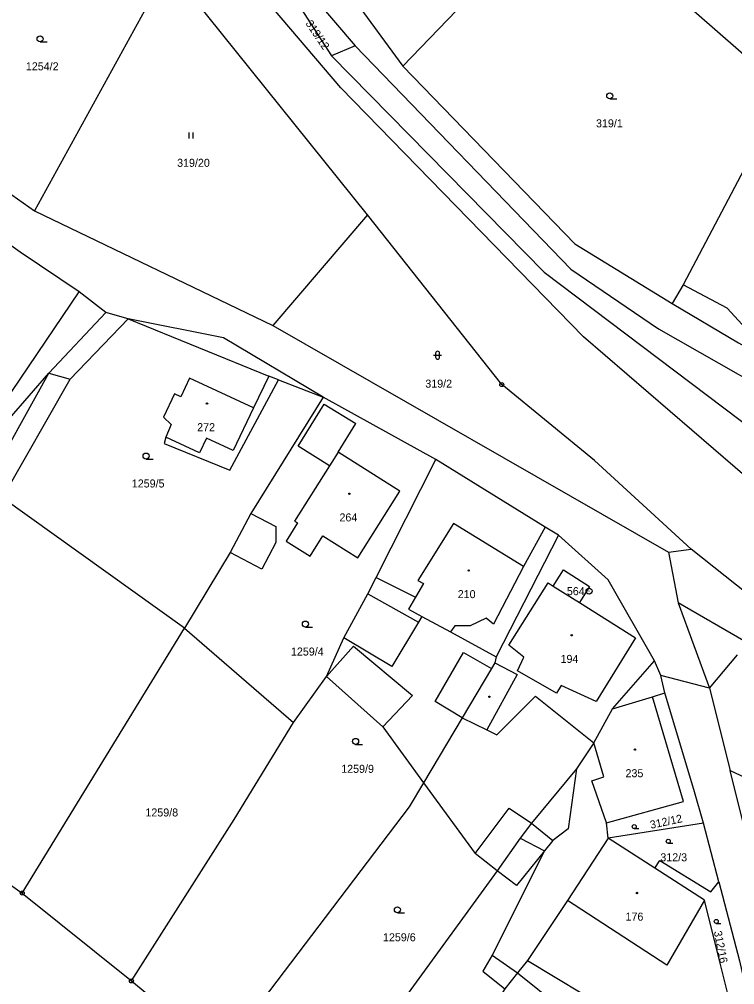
# Model space of a CAD drawing. Extents: x -745926 to -742978, y -968282 to -965689.
# Drawn here: x -745276.5 to -745187.1, y -967037.5 to -966916.9 of the extents above; entities that cross this region are included whole.
import ezdxf

# ---------------------------------------------------------------- set-up
doc = ezdxf.new("R2010")
doc.units = 0
for name, color, linetype in [('Hranice parcel', 7, 'Continuous'), ('Parcelní čísla', 7, 'Continuous'), ('Poz předměty', 7, 'Continuous'), ('Vnitřní kresba', 7, 'Continuous'), ('Značky bodu BP', 7, 'Continuous'), ('Značky budov', 7, 'Continuous'), ('Značky kultur', 7, 'Continuous')]:
    doc.layers.add(name, color=color, linetype=linetype)

msp = doc.modelspace()

# ---------------------------------------------------------------- linework, layer by layer
at = {"layer": 'Hranice parcel'}
for p, q in [((-745180.55, -966926.05), (-745208.11, -966901.93)), ((-745249.76, -966902.34), (-745237.49, -966921.45)), ((-745249.76, -966902.34), (-745234.53, -966920.19)), ((-745239.47, -966907.89), (-745228.55, -966922.71)), ((-745233, -966941.3), (-745257.76, -966910.48)), ((-745259.41, -966913.16), (-745274.6, -966940.8)), ((-745234.53, -966920.19), (-745237.49, -966921.45)), ((-745274.6, -966940.8), (-745244.81, -966955.11)), ((-745233, -966941.3), (-745244.81, -966955.11)), ((-745270.13, -966961.82), (-745262.91, -966954.27)), ((-745244.81, -966955.11), (-745195.35, -966983.42)), ((-745224.43, -966971.87), (-745238.53, -966964.08)), ((-745210.8, -966980.3), (-745224.43, -966971.87)), ((-745209.1, -966981.3), (-745210.8, -966980.3)), ((-745209.1, -966981.3), (-745216.9, -966996.5)), ((-745195.35, -966983.42), (-745192.52, -966983.04)), ((-745195.35, -966983.42), (-745194.15, -966989.75)), ((-745194.15, -966989.75), (-745190.26, -967000.41)), ((-745276.14, -967026.01), (-745255.84, -966992.94)), ((-745255.84, -966992.94), (-745242.24, -967004.7)), ((-745196.33, -966998.82), (-745197.1, -966997)), ((-745190.26, -967000.41), (-745196.33, -966998.82)), ((-745195.83, -967001.01), (-745196.33, -966998.82)), ((-745190.26, -967000.41), (-745187.66, -967010.71)), ((-745187.66, -967010.71), (-745185.09, -967011.89)), ((-745185.48, -967019.4), (-745187.66, -967010.71)), ((-745191.01, -967017.27), (-745202.9, -967019.17)), ((-745189.08, -967024.61), (-745191.01, -967017.27)), ((-745284.25, -967020.3), (-745276.14, -967026.01)), ((-745213.9, -967019.17), (-745210.87, -967020.73)), ((-745197.09, -967022.9), (-745202.9, -967019.17)), ((-745190.87, -967026.9), (-745197.09, -967022.9)), ((-745190.06, -967025.85), (-745189.08, -967024.61)), ((-745276.14, -967026.01), (-745262.49, -967036.98)), ((-745213, -967034.43), (-745214.25, -967035.97)), ((-745214.25, -967035.97), (-745208.81, -967040.3)), ((-745262.49, -967036.98), (-745251.29, -967046.18))]:
    msp.add_line(p, q, dxfattribs=at)
for points in [[(-745228.55, -966922.71), (-745214, -966907.56), (-745210.46, -966904.18)], [(-745296.89, -966915.01), (-745295, -966919.3), (-745292.7, -966924.7), (-745284.5, -966933.2), (-745279.6, -966937.3), (-745274.6, -966940.8)], [(-745234.53, -966920.19), (-745207.57, -966948.09), (-745196.62, -966955.54), (-745176.42, -966967.01), (-745160.97, -966979.85)], [(-745237.49, -966921.45), (-745210.92, -966948.46), (-745176.19, -966974.63), (-745163.93, -966984.87)], [(-745228.55, -966922.71), (-745207.08, -966944.94), (-745194.89, -966952.37)], [(-745180.55, -966926.05), (-745184.33, -966932.61), (-745193.54, -966950.05), (-745194.89, -966952.37)], [(-745269.03, -966950.92), (-745276.41, -966945.96), (-745284.62, -966940.07)], [(-745192.52, -966983.04), (-745204.6, -966972), (-745216.2, -966962.5), (-745233, -966941.3)], [(-745294.07, -966977.76), (-745279.56, -966966.43), (-745269.03, -966950.92)], [(-745262.91, -966954.27), (-745265.7, -966953.5), (-745269.03, -966950.92)], [(-745194.89, -966952.37), (-745186.63, -966957.3), (-745183.99, -966958.75), (-745174.52, -966964.81), (-745165.14, -966972.37), (-745161.18, -966973.19), (-745160.07, -966972.06)], [(-745238.53, -966964.08), (-745250.96, -966956.64), (-745262.91, -966954.27)], [(-745297.5, -967010), (-745294.66, -966999.59), (-745285.71, -966987.42), (-745282.67, -966972.4), (-745272.81, -966961.09), (-745270.13, -966961.82)], [(-745255.84, -966992.94), (-745278.61, -966976.66), (-745270.13, -966961.82)], [(-745255.22, -966961.71), (-745256.32, -966964.02), (-745257.09, -966963.65), (-745258.49, -966966.57), (-745257.5, -966967.5), (-745258.17, -966969.07), (-745258.38, -966969.86), (-745250.17, -966973.19), (-745244.09, -966961.92), (-745245.33, -966961.44), (-745247.23, -966965.42), (-745255.22, -966961.71)], [(-745238.53, -966964.08), (-745247.57, -966978.59), (-745250.16, -966983.48), (-745255.84, -966992.94)], [(-745242.09, -966979.55), (-745241.73, -966979.77), (-745243.16, -966982.04), (-745240.15, -966983.93), (-745238.55, -966981.39), (-745234.19, -966984.14), (-745228.96, -966975.81), (-745236.67, -966970.94), (-745237.73, -966972.63), (-745242.09, -966979.55)], [(-745242.24, -967004.7), (-745238.1, -966998.96), (-745235.95, -966994.13), (-745232.96, -966988.63), (-745231.91, -966986.58), (-745224.43, -966971.87)], [(-745210.8, -966980.3), (-745213.5, -966985.23), (-745222.22, -966979.86), (-745226.68, -966986.95), (-745226, -966987.35), (-745227, -966989.07), (-745227.87, -966990.56), (-745226.19, -966991.46), (-745222.6, -966993.38), (-745216.9, -966996.5)], [(-745197.1, -966997), (-745202.9, -966986.9), (-745209.1, -966981.3)], [(-744949.24, -967094.01), (-745019.94, -967072.91), (-745023.12, -967071.72), (-745025.11, -967070.97), (-745031.23, -967068.81), (-745033.88, -967067.77), (-745037.92, -967066.16), (-745085.77, -967047.22), (-745088.65, -967046.08), (-745106.77, -967038.91), (-745143.53, -967017.02), (-745180, -966993), (-745192.52, -966983.04)], [(-745163.31, -967008.4), (-745185.95, -966994.52), (-745194.15, -966989.75)], [(-745216.9, -966996.5), (-745217.07, -966997.26), (-745217.48, -966997.94), (-745221.16, -967004.14)], [(-745204.72, -967007.26), (-745202.36, -967003), (-745197.1, -966997)], [(-745202.9, -967019.17), (-745203.11, -967017.22), (-745193.48, -967014.55), (-745197.38, -967001.48), (-745195.83, -967001.01)], [(-745191.01, -967017.27), (-745192.12, -967013.35), (-745195.83, -967001.01)], [(-745221.16, -967004.14), (-745218.08, -967005.6), (-745216.84, -967006.24), (-745211.97, -967001.43), (-745204.72, -967007.26)], [(-745221.16, -967004.14), (-745225.97, -967012.23), (-745227.76, -967015.24), (-745251.29, -967046.18)], [(-745262.49, -967036.98), (-745249.66, -967016.81), (-745242.24, -967004.7)], [(-745204.72, -967007.26), (-745206.85, -967010.49), (-745212.49, -967017.26), (-745213.9, -967019.17)], [(-745213.9, -967019.17), (-745216.8, -967023.23), (-745240.35, -967055.61)], [(-745202.9, -967019.17), (-745207.97, -967026.92), (-745211.83, -967032.7), (-745213, -967034.43)], [(-745210.87, -967020.73), (-745217.39, -967033.77), (-745214.25, -967035.97)], [(-745197.09, -967022.9), (-745196.47, -967021.93), (-745190.06, -967025.85)], [(-745189.08, -967024.61), (-745186.49, -967034.46), (-745184.74, -967042.18)], [(-745187.27, -967042.62), (-745187.96, -967038.61), (-745188.97, -967034.61), (-745190.87, -967026.9)], [(-745214.25, -967035.97), (-745215.81, -967037.95), (-745222.69, -967048.89), (-745237.4, -967072.23), (-745240.22, -967071.25)]]:
    msp.add_lwpolyline(points, dxfattribs=at)
at = {"layer": 'Poz předměty'}
for p, q in [((-745236.31, -966925.45), (-745250.92, -966908.25)), ((-745205.98, -966956.55), (-745236.31, -966925.45)), ((-745176.95, -966981.55), (-745205.98, -966956.55))]:
    msp.add_line(p, q, dxfattribs=at)
at = {"layer": 'Vnitřní kresba'}
for p, q in [((-745188.03, -966952.97), (-745193.54, -966950.05)), ((-745272.81, -966961.09), (-745265.7, -966953.5)), ((-745183.84, -966957.56), (-745188.03, -966952.97)), ((-745262.91, -966954.27), (-745245.33, -966961.44)), ((-745280.51, -966974.94), (-745272.81, -966961.09)), ((-745244.09, -966961.92), (-745238.53, -966964.08)), ((-745247.23, -966965.42), (-745249.77, -966970.73)), ((-745241.64, -966970.21), (-745238.38, -966964.94)), ((-745238.38, -966964.94), (-745234.45, -966967.37)), ((-745236.67, -966970.94), (-745234.45, -966967.37)), ((-745253.96, -966971.03), (-745258.17, -966969.07)), ((-745253.1, -966969.2), (-745253.96, -966971.03)), ((-745249.77, -966970.73), (-745253.1, -966969.2)), ((-745237.73, -966972.63), (-745241.64, -966970.21)), ((-745247.57, -966978.59), (-745244.45, -966980.24)), ((-745244.45, -966980.24), (-745244.44, -966982.24)), ((-745244.44, -966982.24), (-745246.2, -966985.57)), ((-745246.2, -966985.57), (-745250.16, -966983.48)), ((-745213.5, -966985.23), (-745217.24, -966992.44)), ((-745231.91, -966986.58), (-745227, -966989.07)), ((-745209.78, -966987.67), (-745208.51, -966985.65)), ((-745208.51, -966985.65), (-745205.23, -966987.71)), ((-745215.33, -966995.05), (-745210.42, -966987.27)), ((-745210.42, -966987.27), (-745209.78, -966987.67)), ((-745209.78, -966987.67), (-745206.49, -966989.73)), ((-745205.23, -966987.71), (-745206.49, -966989.73)), ((-745232.96, -966988.63), (-745226.61, -966992.16)), ((-745206.49, -966989.73), (-745199.48, -966994.14)), ((-745226.61, -966992.16), (-745229.93, -966997.72)), ((-745226.19, -966991.46), (-745226.61, -966992.16)), ((-745222.07, -966992.61), (-745222.6, -966993.38)), ((-745220.15, -966992.65), (-745222.07, -966992.61)), ((-745218.16, -966991.66), (-745220.15, -966992.65)), ((-745217.24, -966992.44), (-745218.16, -966991.66)), ((-745229.93, -966997.72), (-745235.95, -966994.13)), ((-745199.48, -966994.14), (-745204.39, -967002.07)), ((-745238.1, -966998.96), (-745234.73, -966995.17)), ((-745234.73, -966995.17), (-745227.35, -967001.33)), ((-745224.51, -967002.07), (-745221, -966995.97)), ((-745221, -966995.97), (-745217.48, -966997.94)), ((-745213.45, -966996.55), (-745215.33, -966995.05)), ((-745217.07, -966997.26), (-745214.28, -966998.72)), ((-745214.25, -966998.24), (-745213.45, -966996.55)), ((-745190.26, -967000.41), (-745186.74, -966996.27)), ((-745209.37, -967001.03), (-745214.25, -966998.24)), ((-745231.05, -967005.26), (-745238.1, -966998.96)), ((-745214.28, -966998.72), (-745218.08, -967005.6)), ((-745208.8, -967000.1), (-745209.37, -967001.03)), ((-745204.39, -967002.07), (-745208.8, -967000.1)), ((-745227.35, -967001.33), (-745231.05, -967005.26)), ((-745221.16, -967004.14), (-745224.51, -967002.07)), ((-745202.36, -967003), (-745197.38, -967001.48)), ((-745231.05, -967005.26), (-745225.97, -967012.23)), ((-745203.47, -967011.51), (-745204.72, -967007.26)), ((-745206.85, -967010.49), (-745207.9, -967018)), ((-745204.94, -967011.97), (-745203.47, -967011.51)), ((-745225.97, -967012.23), (-745219.55, -967021.05)), ((-745203.11, -967017.22), (-745204.94, -967011.97)), ((-745219.55, -967021.05), (-745215.26, -967015.4)), ((-745215.26, -967015.4), (-745212.49, -967017.26)), ((-745212.49, -967017.26), (-745209.82, -967019.43)), ((-745207.9, -967018), (-745209.82, -967019.43)), ((-745209.82, -967019.43), (-745210.87, -967020.73)), ((-745216.8, -967023.23), (-745219.55, -967021.05)), ((-745210.87, -967020.73), (-745214.35, -967025.07)), ((-745214.35, -967025.07), (-745216.8, -967023.23)), ((-745195.59, -967035), (-745207.97, -967026.92)), ((-745190.87, -967026.9), (-745195.59, -967035)), ((-745217.39, -967033.77), (-745218.56, -967035.78)), ((-745213, -967034.43), (-745206.07, -967038.58)), ((-745218.56, -967035.78), (-745215.81, -967037.95))]:
    msp.add_line(p, q, dxfattribs=at)
at = {"layer": 'Značky bodu BP'}
for centre, radius in [((-745216.2, -966962.5), 0.25), ((-745216.2, -966962.5), 0.0152), ((-745205.3, -966988.3), 0.375), ((-745205.3, -966988.3), 0.015), ((-745276.14, -967026.01), 0.25), ((-745276.14, -967026.01), 0.0152), ((-745262.49, -967036.98), 0.25), ((-745262.49, -967036.98), 0.0152)]:
    msp.add_circle(centre, radius, dxfattribs=at)
at = {"layer": 'Značky budov'}
for centre in [(-745253.04, -966964.87), (-745235.25, -966976.14), (-745220.34, -966985.72), (-745207.45, -966993.81), (-745217.74, -967001.49), (-745199.56, -967008.09), (-745199.31, -967026)]:
    msp.add_circle(centre, 0.0875, dxfattribs=at)
at = {"layer": 'Značky kultur'}
for p, q in [((-745273.91, -966919.7), (-745273.03, -966919.7)), ((-745202.72, -966926.82), (-745201.84, -966926.82)), ((-745255.27, -966931.75), (-745255.27, -966931)), ((-745254.77, -966931.75), (-745254.77, -966931)), ((-745224.72, -966958.83), (-745223.72, -966958.83)), ((-745224.47, -966958.58), (-745224.47, -966959.08)), ((-745223.97, -966959.08), (-745223.97, -966958.58)), ((-745260.66, -966971.8), (-745259.78, -966971.8)), ((-745240.75, -966992.79), (-745239.87, -966992.79)), ((-745234.47, -967007.44), (-745233.59, -967007.44)), ((-745199.65, -967017.96), (-745199.06, -967017.96)), ((-745195.4, -967019.79), (-745194.81, -967019.79)), ((-745229.25, -967028.48), (-745228.37, -967028.48)), ((-745189.4, -967029.8), (-745188.81, -967029.8))]:
    msp.add_line(p, q, dxfattribs=at)
for centre, radius in [((-745273.91, -966919.32), 0.375), ((-745202.72, -966926.44), 0.375), ((-745260.66, -966971.42), 0.375), ((-745240.75, -966992.41), 0.375), ((-745234.47, -967007.06), 0.375), ((-745199.65, -967017.71), 0.251), ((-745195.4, -967019.54), 0.251), ((-745229.25, -967028.1), 0.375), ((-745189.4, -967029.55), 0.251)]:
    msp.add_circle(centre, radius, dxfattribs=at)
for centre, start, end in [((-745224.22, -966958.58), 0, 180), ((-745224.22, -966959.08), 180, 359.9879)]:
    msp.add_arc(centre, 0.25, start, end, dxfattribs=at)

# ---------------------------------------------------------------- texts
at = {"layer": 'Parcelní čísla'}
for s, rotation, p in [('319/12', 304, (-745240.78, -966917.39)), ('312/12', 12, (-745197.57, -967017.99)), ('312/16', 281, (-745189.71, -967030.82))]:
    msp.add_text(s, height=1, rotation=rotation, dxfattribs=at).set_placement(p)
for s, p in [('1254/2', (-745275.68, -966923.25)), ('319/1', (-745204.43, -966930.37)), ('319/20', (-745256.78, -966935.3)), ('319/2', (-745225.76, -966962.88)), ('272', (-745254.27, -966968.32)), ('1259/5', (-745262.44, -966975.35)), ('264', (-745236.49, -966979.59)), ('210', (-745221.71, -966989.17)), ('1259/4', (-745242.55, -966996.34)), ('194', (-745208.86, -966997.26)), ('1259/9', (-745236.27, -967010.99)), ('235', (-745200.74, -967011.54)), ('1259/8', (-745260.74, -967016.44)), ('312/3', (-745196.39, -967022.04)), ('176', (-745200.74, -967029.45)), ('1259/6', (-745231.05, -967032.03))]:
    msp.add_text(s, height=1, dxfattribs=at).set_placement(p)
at = {"layer": 'Značky bodu BP'}
msp.add_text('564', height=1, dxfattribs=at).set_placement((-745208.07, -966988.8))

doc.saveas('drawing.dxf')
